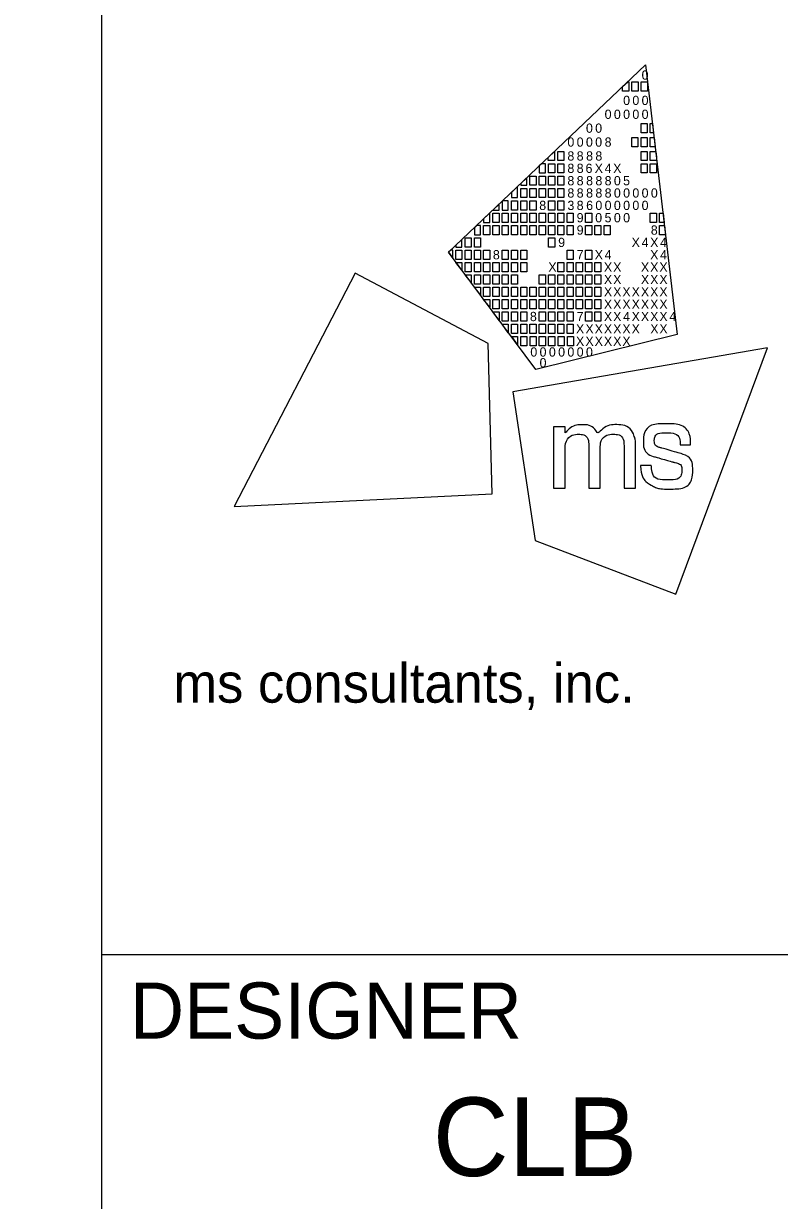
# Model space of a CAD drawing. Extents: x -0.2 to 34, y 0 to 22.
# Drawn here: x 31.86 to 33.207, y 2.061 to 4.16 of the extents above; entities that cross this region are included whole.
import ezdxf

# ---------------------------------------------------------------- set-up
doc = ezdxf.new("R2010")
doc.units = 0
for name, color, linetype in [('SC_Scratch1', 7, 'Continuous'), ('SH_Border', 7, 'Continuous'), ('SH_Data', 7, 'Continuous')]:
    doc.layers.add(name, color=color, linetype=linetype)

msp = doc.modelspace()

# ---------------------------------------------------------------- linework, layer by layer
at = {"layer": 'SC_Scratch1'}
msp.add_lwpolyline([(32, 21.5), (1.5, 21.5), (1.5, 0.5), (32, 0.5)], close=True, dxfattribs=at)
at = {"layer": 'SH_Border'}
for p, q in [((32, 0.5), (32, 21.5)), ((32.6175, 3.7519), (32.9688, 4.0861)), ((32.9688, 4.0861), (32.9688, 4.0861)), ((32.9688, 4.0861), (33.0253, 3.6052)), ((32.773, 3.543), (32.6175, 3.7519)), ((33.0253, 3.6052), (32.773, 3.543)), ((32, 2.5), (33.5, 2.5))]:
    msp.add_line(p, q, dxfattribs=at)
for points in [[(32.9279, 4.0472), (32.9369, 4.0558), (32.9389, 4.0558), (32.9389, 4.0393), (32.9279, 4.0393)], [(32.9444, 4.0558), (32.9554, 4.0558), (32.9554, 4.0393), (32.9444, 4.0393)], [(32.9609, 4.0558), (32.9719, 4.0558), (32.9719, 4.0393), (32.9609, 4.0393)], [(32.9606, 3.9815), (32.9716, 3.9815), (32.9716, 3.965), (32.9606, 3.965)], [(32.9771, 3.9815), (32.9811, 3.9815), (32.983, 3.965), (32.9771, 3.965)], [(32.9441, 3.9567), (32.9551, 3.9567), (32.9551, 3.9402), (32.9441, 3.9402)], [(32.9606, 3.9567), (32.9716, 3.9567), (32.9716, 3.9402), (32.9606, 3.9402)], [(32.9771, 3.9567), (32.984, 3.9567), (32.9859, 3.9402), (32.9771, 3.9402)], [(32.7953, 3.9211), (32.8064, 3.9316), (32.8064, 3.9154), (32.7953, 3.9154)], [(32.8123, 3.9319), (32.8233, 3.9319), (32.8233, 3.9154), (32.8123, 3.9154)], [(32.9606, 3.9319), (32.9716, 3.9319), (32.9716, 3.9154), (32.9606, 3.9154)], [(32.9771, 3.9319), (32.9869, 3.9319), (32.9881, 3.9218), (32.9881, 3.9154), (32.9771, 3.9154)], [(32.7958, 3.9099), (32.8068, 3.9099), (32.8068, 3.8934), (32.7958, 3.8934)], [(32.8123, 3.9099), (32.8233, 3.9099), (32.8233, 3.8934), (32.8123, 3.8934)], [(32.9606, 3.9099), (32.9716, 3.9099), (32.9716, 3.8934), (32.9606, 3.8934)], [(32.9771, 3.9099), (32.9881, 3.9099), (32.9881, 3.8934), (32.9771, 3.8934)], [(32.7627, 3.8879), (32.7737, 3.8879), (32.7737, 3.8714), (32.7627, 3.8714)], [(32.7793, 3.8879), (32.7903, 3.8879), (32.7903, 3.8714), (32.7793, 3.8714)], [(32.7958, 3.8879), (32.8068, 3.8879), (32.8068, 3.8714), (32.7958, 3.8714)], [(32.8123, 3.8879), (32.8233, 3.8879), (32.8233, 3.8714), (32.8123, 3.8714)], [(32.7462, 3.8659), (32.7572, 3.8659), (32.7572, 3.8494), (32.7462, 3.8494)], [(32.7627, 3.8659), (32.7737, 3.8659), (32.7737, 3.8494), (32.7627, 3.8494)], [(32.7793, 3.8659), (32.7903, 3.8659), (32.7903, 3.8494), (32.7793, 3.8494)], [(32.7958, 3.8659), (32.8068, 3.8659), (32.8068, 3.8494), (32.7958, 3.8494)], [(32.8123, 3.8659), (32.8233, 3.8659), (32.8233, 3.8494), (32.8123, 3.8494)], [(32.7297, 3.8439), (32.7407, 3.8439), (32.7407, 3.8273), (32.7297, 3.8273)], [(32.7462, 3.8439), (32.7572, 3.8439), (32.7572, 3.8273), (32.7462, 3.8273)], [(32.7627, 3.8439), (32.7737, 3.8439), (32.7737, 3.8273), (32.7627, 3.8273)], [(32.7958, 3.8439), (32.8068, 3.8439), (32.8068, 3.8273), (32.7958, 3.8273)], [(32.8123, 3.8439), (32.8233, 3.8439), (32.8233, 3.8273), (32.8123, 3.8273)], [(32.6967, 3.8218), (32.7077, 3.8218), (32.7077, 3.8053), (32.6967, 3.8053)], [(32.7132, 3.8218), (32.7242, 3.8218), (32.7242, 3.8053), (32.7132, 3.8053)], [(32.7297, 3.8218), (32.7407, 3.8218), (32.7407, 3.8053), (32.7297, 3.8053)], [(32.7462, 3.8218), (32.7572, 3.8218), (32.7572, 3.8053), (32.7462, 3.8053)], [(32.7627, 3.8218), (32.7737, 3.8218), (32.7737, 3.8053), (32.7627, 3.8053)], [(32.7793, 3.8218), (32.7903, 3.8218), (32.7903, 3.8053), (32.7793, 3.8053)], [(32.7958, 3.8218), (32.8068, 3.8218), (32.8068, 3.8053), (32.7958, 3.8053)], [(32.8123, 3.8218), (32.8233, 3.8218), (32.8233, 3.8053), (32.8123, 3.8053)], [(32.8288, 3.8218), (32.8398, 3.8218), (32.8398, 3.8053), (32.8288, 3.8053)], [(32.8618, 3.8218), (32.8728, 3.8218), (32.8728, 3.8053), (32.8618, 3.8053)], [(32.9771, 3.8218), (32.9881, 3.8218), (32.9881, 3.8053), (32.9771, 3.8053)], [(32.9935, 3.8218), (32.9998, 3.8218), (33.0018, 3.8053), (32.9935, 3.8053)], [(32.6802, 3.7998), (32.6912, 3.7998), (32.6912, 3.7833), (32.6802, 3.7833)], [(32.6967, 3.7998), (32.7077, 3.7998), (32.7077, 3.7833), (32.6967, 3.7833)], [(32.7132, 3.7998), (32.7242, 3.7998), (32.7242, 3.7833), (32.7132, 3.7833)], [(32.7297, 3.7998), (32.7407, 3.7998), (32.7407, 3.7833), (32.7297, 3.7833)], [(32.7462, 3.7998), (32.7572, 3.7998), (32.7572, 3.7833), (32.7462, 3.7833)], [(32.7627, 3.7998), (32.7737, 3.7998), (32.7737, 3.7833), (32.7627, 3.7833)], [(32.7793, 3.7998), (32.7903, 3.7998), (32.7903, 3.7833), (32.7793, 3.7833)], [(32.7958, 3.7998), (32.8068, 3.7998), (32.8068, 3.7833), (32.7958, 3.7833)], [(32.8123, 3.7998), (32.8233, 3.7998), (32.8233, 3.7833), (32.8123, 3.7833)], [(32.8288, 3.7998), (32.8398, 3.7998), (32.8398, 3.7833), (32.8288, 3.7833)], [(32.8618, 3.7998), (32.8728, 3.7998), (32.8728, 3.7833), (32.8618, 3.7833)], [(32.8783, 3.7998), (32.8893, 3.7998), (32.8893, 3.7833), (32.8783, 3.7833)], [(32.8947, 3.7998), (32.9057, 3.7998), (32.9057, 3.7833), (32.8947, 3.7833)], [(32.9935, 3.7998), (33.0024, 3.7998), (33.0044, 3.7833), (32.9935, 3.7833)], [(32.6471, 3.7778), (32.6581, 3.7778), (32.6581, 3.7613), (32.6471, 3.7613)], [(32.6637, 3.7778), (32.6747, 3.7778), (32.6747, 3.7613), (32.6637, 3.7613)], [(32.7958, 3.7778), (32.8068, 3.7778), (32.8068, 3.7613), (32.7958, 3.7613)], [(32.6306, 3.7558), (32.6416, 3.7558), (32.6416, 3.7393), (32.6306, 3.7393)], [(32.6471, 3.7558), (32.6581, 3.7558), (32.6581, 3.7393), (32.6471, 3.7393)], [(32.6637, 3.7558), (32.6747, 3.7558), (32.6747, 3.7393), (32.6637, 3.7393)], [(32.6802, 3.7558), (32.6912, 3.7558), (32.6912, 3.7393), (32.6802, 3.7393)], [(32.7132, 3.7558), (32.7242, 3.7558), (32.7242, 3.7393), (32.7132, 3.7393)], [(32.7297, 3.7558), (32.7407, 3.7558), (32.7407, 3.7393), (32.7297, 3.7393)], [(32.7462, 3.7558), (32.7572, 3.7558), (32.7572, 3.7393), (32.7462, 3.7393)], [(32.8288, 3.7558), (32.8398, 3.7558), (32.8398, 3.7393), (32.8288, 3.7393)], [(32.8618, 3.7558), (32.8728, 3.7558), (32.8728, 3.7393), (32.8618, 3.7393)], [(32.6306, 3.7338), (32.6416, 3.7338), (32.6416, 3.72)], [(32.6471, 3.7338), (32.6581, 3.7338), (32.6581, 3.7173), (32.6471, 3.7173)], [(32.6637, 3.7338), (32.6747, 3.7338), (32.6747, 3.7173), (32.6637, 3.7173)], [(32.6802, 3.7338), (32.6912, 3.7338), (32.6912, 3.7173), (32.6802, 3.7173)], [(32.6967, 3.7338), (32.7077, 3.7338), (32.7077, 3.7173), (32.6967, 3.7173)], [(32.7132, 3.7338), (32.7242, 3.7338), (32.7242, 3.7173), (32.7132, 3.7173)], [(32.7297, 3.7338), (32.7407, 3.7338), (32.7407, 3.7173), (32.7297, 3.7173)], [(32.7462, 3.7338), (32.7572, 3.7338), (32.7572, 3.7173), (32.7462, 3.7173)], [(32.8123, 3.7338), (32.8233, 3.7338), (32.8233, 3.7173), (32.8123, 3.7173)], [(32.8288, 3.7338), (32.8398, 3.7338), (32.8398, 3.7173), (32.8288, 3.7173)], [(32.8453, 3.7338), (32.8563, 3.7338), (32.8563, 3.7173), (32.8453, 3.7173)], [(32.8618, 3.7338), (32.8728, 3.7338), (32.8728, 3.7173), (32.8618, 3.7173)], [(32.8783, 3.7338), (32.8893, 3.7338), (32.8893, 3.7173), (32.8783, 3.7173)], [(32.6471, 3.7117), (32.6581, 3.7117), (32.6581, 3.698)], [(32.6637, 3.7117), (32.6747, 3.7117), (32.6747, 3.6952), (32.6637, 3.6952)], [(32.6802, 3.7117), (32.6912, 3.7117), (32.6912, 3.6952), (32.6802, 3.6952)], [(32.6967, 3.7117), (32.7077, 3.7117), (32.7077, 3.6952), (32.6967, 3.6952)], [(32.7132, 3.7117), (32.7242, 3.7117), (32.7242, 3.6952), (32.7132, 3.6952)], [(32.7297, 3.7117), (32.7407, 3.7117), (32.7407, 3.6952), (32.7297, 3.6952)], [(32.7793, 3.7117), (32.7903, 3.7117), (32.7903, 3.6952), (32.7793, 3.6952)], [(32.7958, 3.7117), (32.8068, 3.7117), (32.8068, 3.6952), (32.7958, 3.6952)], [(32.8123, 3.7117), (32.8233, 3.7117), (32.8233, 3.6952), (32.8123, 3.6952)], [(32.8288, 3.7117), (32.8398, 3.7117), (32.8398, 3.6952), (32.8288, 3.6952)], [(32.8453, 3.7117), (32.8563, 3.7117), (32.8563, 3.6952), (32.8453, 3.6952)], [(32.8618, 3.7117), (32.8728, 3.7117), (32.8728, 3.6952), (32.8618, 3.6952)], [(32.8783, 3.7117), (32.8893, 3.7117), (32.8893, 3.6952), (32.8783, 3.6952)], [(32.6637, 3.6897), (32.6747, 3.6897), (32.6747, 3.676)], [(32.6747, 3.6897), (32.6747, 3.6897), (32.6747, 3.6897)], [(32.6802, 3.6897), (32.6912, 3.6897), (32.6912, 3.6732), (32.6802, 3.6732)], [(32.6967, 3.6897), (32.7077, 3.6897), (32.7077, 3.6732), (32.6967, 3.6732)], [(32.7132, 3.6897), (32.7242, 3.6897), (32.7242, 3.6732), (32.7132, 3.6732)], [(32.7297, 3.6897), (32.7407, 3.6897), (32.7407, 3.6732), (32.7297, 3.6732)], [(32.7462, 3.6897), (32.7572, 3.6897), (32.7572, 3.6732), (32.7462, 3.6732)], [(32.7627, 3.6897), (32.7737, 3.6897), (32.7737, 3.6732), (32.7627, 3.6732)], [(32.7793, 3.6897), (32.7903, 3.6897), (32.7903, 3.6732), (32.7793, 3.6732)], [(32.7958, 3.6897), (32.8068, 3.6897), (32.8068, 3.6732), (32.7958, 3.6732)], [(32.8123, 3.6897), (32.8233, 3.6897), (32.8233, 3.6732), (32.8123, 3.6732)], [(32.8288, 3.6897), (32.8398, 3.6897), (32.8398, 3.6732), (32.8288, 3.6732)], [(32.8453, 3.6897), (32.8563, 3.6897), (32.8563, 3.6732), (32.8453, 3.6732)], [(32.8618, 3.6897), (32.8728, 3.6897), (32.8728, 3.6732), (32.8618, 3.6732)], [(32.8783, 3.6897), (32.8893, 3.6897), (32.8893, 3.6732), (32.8783, 3.6732)], [(32.6802, 3.6677), (32.6912, 3.6677), (32.6912, 3.654)], [(32.6967, 3.6677), (32.7077, 3.6677), (32.7077, 3.6512), (32.6967, 3.6512)], [(32.7132, 3.6677), (32.7242, 3.6677), (32.7242, 3.6512), (32.7132, 3.6512)], [(32.7297, 3.6677), (32.7407, 3.6677), (32.7407, 3.6512), (32.7297, 3.6512)], [(32.7462, 3.6677), (32.7572, 3.6677), (32.7572, 3.6512), (32.7462, 3.6512)], [(32.7627, 3.6677), (32.7737, 3.6677), (32.7737, 3.6512), (32.7627, 3.6512)], [(32.7793, 3.6677), (32.7903, 3.6677), (32.7903, 3.6512), (32.7793, 3.6512)], [(32.7958, 3.6677), (32.8068, 3.6677), (32.8068, 3.6512), (32.7958, 3.6512)], [(32.8123, 3.6677), (32.8233, 3.6677), (32.8233, 3.6512), (32.8123, 3.6512)], [(32.8288, 3.6677), (32.8398, 3.6677), (32.8398, 3.6512), (32.8288, 3.6512)], [(32.8453, 3.6677), (32.8563, 3.6677), (32.8563, 3.6512), (32.8453, 3.6512)], [(32.8618, 3.6677), (32.8728, 3.6677), (32.8728, 3.6512), (32.8618, 3.6512)], [(32.8783, 3.6677), (32.8893, 3.6677), (32.8893, 3.6512), (32.8783, 3.6512)], [(32.7077, 3.6305), (32.6965, 3.6457), (32.7077, 3.6457)], [(32.7132, 3.6457), (32.7242, 3.6457), (32.7242, 3.6292), (32.7132, 3.6292)], [(32.7297, 3.6457), (32.7407, 3.6457), (32.7407, 3.6292), (32.7297, 3.6292)], [(32.7462, 3.6457), (32.7572, 3.6457), (32.7572, 3.6292), (32.7462, 3.6292)], [(32.7793, 3.6457), (32.7903, 3.6457), (32.7903, 3.6292), (32.7793, 3.6292)], [(32.7958, 3.6457), (32.8068, 3.6457), (32.8068, 3.6292), (32.7958, 3.6292)], [(32.8123, 3.6457), (32.8233, 3.6457), (32.8233, 3.6292), (32.8123, 3.6292)], [(32.8288, 3.6457), (32.8398, 3.6457), (32.8398, 3.6292), (32.8288, 3.6292)], [(32.8618, 3.6457), (32.8728, 3.6457), (32.8728, 3.6292), (32.8618, 3.6292)], [(32.8783, 3.6457), (32.8893, 3.6457), (32.8893, 3.6292), (32.8783, 3.6292)], [(32.724, 3.6082), (32.7132, 3.6237), (32.7242, 3.6237)], [(32.7297, 3.6237), (32.7407, 3.6237), (32.7407, 3.6072), (32.7297, 3.6072)], [(32.7462, 3.6237), (32.7572, 3.6237), (32.7572, 3.6072), (32.7462, 3.6072)], [(32.7627, 3.6237), (32.7737, 3.6237), (32.7737, 3.6072), (32.7627, 3.6072)], [(32.7793, 3.6237), (32.7903, 3.6237), (32.7903, 3.6072), (32.7793, 3.6072)], [(32.7958, 3.6237), (32.8068, 3.6237), (32.8068, 3.6072), (32.7958, 3.6072)], [(32.8123, 3.6237), (32.8233, 3.6237), (32.8233, 3.6072), (32.8123, 3.6072)], [(32.8288, 3.6237), (32.8398, 3.6237), (32.8398, 3.6072), (32.8288, 3.6072)], [(32.7302, 3.6017), (32.7407, 3.6017), (32.7408, 3.5875)], [(32.7463, 3.6017), (32.7573, 3.6017), (32.7573, 3.5852), (32.7463, 3.5852)], [(32.763, 3.6017), (32.774, 3.6017), (32.774, 3.5852), (32.763, 3.5852)], [(32.7794, 3.6017), (32.7904, 3.6017), (32.7904, 3.5852), (32.7794, 3.5852)], [(32.796, 3.6017), (32.807, 3.6017), (32.807, 3.5852), (32.796, 3.5852)], [(32.8129, 3.6017), (32.8239, 3.6017), (32.8239, 3.5851), (32.8129, 3.5851)], [(32.8296, 3.6017), (32.8406, 3.6017), (32.8406, 3.5851), (32.8296, 3.5851)]]:
    msp.add_lwpolyline(points, close=True, dxfattribs=at)
for points in [[(32.7903, 3.9099), (32.7836, 3.9099), (32.7793, 3.9058), (32.7793, 3.8934), (32.7903, 3.8934), (32.7903, 3.9099)], [(32.7572, 3.8849), (32.7462, 3.8744), (32.7462, 3.8714), (32.7572, 3.8714), (32.7572, 3.8849)], [(32.7407, 3.8691), (32.7297, 3.8587), (32.7297, 3.8494), (32.7407, 3.8494), (32.7407, 3.8691)], [(32.7242, 3.8439), (32.7141, 3.8439), (32.7132, 3.843), (32.7132, 3.8273), (32.7242, 3.8273), (32.7242, 3.8439)], [(32.6912, 3.822), (32.6802, 3.8115), (32.6802, 3.8053), (32.6912, 3.8053), (32.6912, 3.822)], [(32.7077, 3.8377), (32.6968, 3.8273), (32.7077, 3.8273), (32.7077, 3.8377)], [(32.6747, 3.7998), (32.6679, 3.7998), (32.6637, 3.7958), (32.6637, 3.7833), (32.6747, 3.7833), (32.6747, 3.7998)], [(32.6416, 3.7749), (32.6306, 3.7644), (32.6306, 3.7613), (32.6416, 3.7613), (32.6416, 3.7749)], [(32.6251, 3.7558), (32.6216, 3.7558), (32.6175, 3.7519), (32.6251, 3.7417), (32.6251, 3.7558)], [(32.4512, 3.7149), (32.2359, 3.2988), (32.6956, 3.3215), (32.6884, 3.5892), (32.4512, 3.7149)], [(33.0229, 3.1422), (33.1859, 3.5814), (32.7324, 3.5029), (32.7722, 3.2381), (33.0229, 3.1422)]]:
    msp.add_lwpolyline(points, dxfattribs=at)
for points in [[(32.8048, 3.3315), (32.8048, 3.3315), (32.8048, 3.4409), (32.8048, 3.4409), (32.8048, 3.4409), (32.8255, 3.4409), (32.8255, 3.4409), (32.8255, 3.4409), (32.8255, 3.4297), (32.8255, 3.4297), (32.8346, 3.4399), (32.8457, 3.4445), (32.8555, 3.4445), (32.8688, 3.4445), (32.8791, 3.4372), (32.8837, 3.4266), (32.8915, 3.4381), (32.905, 3.4446), (32.9166, 3.4446), (32.9325, 3.4446), (32.9451, 3.435), (32.9494, 3.4213), (32.9494, 3.4212), (32.9494, 3.4212), (32.9494, 3.4212), (32.9501, 3.419), (32.9506, 3.4172), (32.9506, 3.4071), (32.9506, 3.4071), (32.9506, 3.3314), (32.9506, 3.3314), (32.9506, 3.3314), (32.9303, 3.3314), (32.9303, 3.3314), (32.9303, 3.3314), (32.9303, 3.4048), (32.9303, 3.4048), (32.9303, 3.4201), (32.9219, 3.4274), (32.911, 3.4274), (32.8995, 3.4274), (32.8879, 3.4171), (32.8879, 3.4001), (32.8879, 3.4001), (32.8879, 3.3315), (32.8879, 3.3315), (32.8879, 3.3315), (32.8674, 3.3315), (32.8674, 3.3315), (32.8674, 3.3315), (32.8674, 3.4059), (32.8674, 3.4059), (32.8674, 3.4203), (32.8588, 3.4274), (32.8496, 3.4274), (32.8384, 3.4274), (32.8254, 3.417), (32.8254, 3.3962), (32.8254, 3.3962), (32.8254, 3.3315), (32.8254, 3.3315), (32.8254, 3.3315), (32.8048, 3.3315), (32.8048, 3.3315)], [(32.9595, 3.3709), (32.9595, 3.3709), (32.9595, 3.3717), (32.9595, 3.3717), (32.9595, 3.3717), (32.9603, 3.3717), (32.9603, 3.3717), (32.9603, 3.3717), (32.9783, 3.3717), (32.9783, 3.3717), (32.9783, 3.3717), (32.9789, 3.3717), (32.9789, 3.3717), (32.9789, 3.3717), (32.979, 3.371), (32.979, 3.371), (32.9803, 3.3554), (32.9887, 3.346), (33.009, 3.346), (33.0273, 3.346), (33.0333, 3.3554), (33.0333, 3.3631), (33.0333, 3.3732), (33.0256, 3.3758), (33.0175, 3.378), (33.0175, 3.378), (32.987, 3.3867), (32.987, 3.3867), (32.972, 3.3909), (32.9648, 3.4019), (32.9648, 3.4142), (32.9648, 3.4303), (32.9768, 3.4462), (33.0052, 3.4462), (33.0348, 3.4462), (33.0489, 3.4285), (33.0489, 3.4095), (33.0489, 3.4095), (33.0489, 3.4087), (33.0489, 3.4087), (33.0489, 3.4087), (33.0482, 3.4087), (33.0482, 3.4087), (33.0482, 3.4087), (33.0312, 3.4087), (33.0312, 3.4087), (33.0312, 3.4087), (33.0305, 3.4087), (33.0305, 3.4087), (33.0305, 3.4087), (33.0305, 3.4094), (33.0305, 3.4094), (33.0301, 3.4208), (33.0226, 3.43), (33.0056, 3.43), (32.9891, 3.43), (32.9843, 3.4218), (32.9843, 3.4157), (32.9843, 3.4108), (32.9869, 3.4059), (32.9959, 3.4033), (32.9959, 3.4033), (33.0255, 3.3948), (33.0255, 3.3948), (33.0462, 3.3889), (33.0527, 3.3777), (33.0527, 3.3639), (33.0527, 3.3462), (33.041, 3.3298), (33.0087, 3.3298), (32.9952, 3.3298), (32.9877, 3.3321), (32.9823, 3.3348), (32.969, 3.3414), (32.9609, 3.3536), (32.9595, 3.3709)]]:
    msp.add_open_spline(points, degree=3, dxfattribs=at)
at = {"layer": 'SH_Data'}
msp.add_line((32.75, 3.5), (32.75, 3.5), dxfattribs=at)

# ---------------------------------------------------------------- texts
at = {"layer": 'SH_Border'}
for s, height, p in [('0', 0.0165, (32.9617, 4.0597)), ('0', 0.0165, (32.9288, 4.0145)), ('0', 0.0165, (32.9452, 4.0145)), ('0', 0.0165, (32.9617, 4.0145)), ('0', 0.0165, (32.8958, 3.9897)), ('0', 0.0165, (32.9123, 3.9897)), ('0', 0.0165, (32.9288, 3.9897)), ('0', 0.0165, (32.9452, 3.9897)), ('0', 0.0165, (32.9617, 3.9897)), ('0', 0.0165, (32.8625, 3.965)), ('0', 0.0165, (32.879, 3.965)), ('0', 0.0165, (32.8295, 3.9402)), ('0', 0.0165, (32.846, 3.9402)), ('0', 0.0165, (32.8625, 3.9402)), ('0', 0.0165, (32.879, 3.9402)), ('8', 0.0165, (32.8958, 3.9402)), ('8', 0.0165, (32.8295, 3.9154)), ('8', 0.0165, (32.846, 3.9154)), ('8', 0.0165, (32.8628, 3.9154)), ('8', 0.0165, (32.8793, 3.9154)), ('8', 0.0165, (32.8295, 3.8934)), ('8', 0.0165, (32.846, 3.8934)), ('6', 0.0165, (32.8618, 3.8934)), ('X', 0.0165, (32.8781, 3.8934)), ('4', 0.0165, (32.8958, 3.8934)), ('X', 0.0165, (32.911, 3.8934)), ('8', 0.0165, (32.8295, 3.8713)), ('8', 0.0165, (32.846, 3.8713)), ('8', 0.0165, (32.8628, 3.8713)), ('8', 0.0165, (32.8794, 3.8713)), ('8', 0.0165, (32.8958, 3.8713)), ('0', 0.0165, (32.9123, 3.8713)), ('5', 0.0165, (32.9287, 3.8713)), ('8', 0.0165, (32.8295, 3.8494)), ('8', 0.0165, (32.846, 3.8494)), ('8', 0.0165, (32.8628, 3.8494)), ('8', 0.0165, (32.8794, 3.8494)), ('8', 0.0165, (32.8958, 3.8494)), ('0', 0.0165, (32.9123, 3.8494)), ('0', 0.0165, (32.9288, 3.8494)), ('0', 0.0165, (32.9452, 3.8494)), ('0', 0.0165, (32.9617, 3.8494)), ('0', 0.0165, (32.9782, 3.8494)), ('8', 0.0165, (32.7793, 3.8273)), ('3', 0.0165, (32.8295, 3.8273)), ('8', 0.0165, (32.846, 3.8273)), ('6', 0.0165, (32.8629, 3.8273)), ('0', 0.0165, (32.8793, 3.8273)), ('0', 0.0165, (32.8958, 3.8273)), ('0', 0.0165, (32.9123, 3.8273)), ('0', 0.0165, (32.9288, 3.8273)), ('0', 0.0165, (32.9452, 3.8273)), ('0', 0.0165, (32.9617, 3.8273)), ('9', 0.0165, (32.846, 3.8053)), ('0', 0.0165, (32.879, 3.8053)), ('5', 0.0165, (32.8957, 3.8053)), ('0', 0.0165, (32.9123, 3.8053)), ('0', 0.0165, (32.9288, 3.8053)), ('9', 0.0165, (32.846, 3.7833)), ('8', 0.0165, (32.9781, 3.7833)), ('9', 0.0165, (32.813, 3.7613)), ('X', 0.0165, (32.9439, 3.7613)), ('4', 0.0165, (32.9617, 3.7613)), ('X', 0.0165, (32.9769, 3.7613)), ('4', 0.0165, (32.9946, 3.7613)), ('8', 0.0165, (32.6967, 3.7393)), ('7', 0.0165, (32.846, 3.7393)), ('X', 0.0165, (32.8781, 3.7393)), ('4', 0.0165, (32.8958, 3.7393)), ('X', 0.0165, (32.9769, 3.7393)), ('4', 0.0165, (32.9946, 3.7393)), ('X', 0.0165, (32.7955, 3.7173)), ('X', 0.0165, (32.8945, 3.7173)), ('X', 0.0165, (32.911, 3.7173)), ('X', 0.0165, (32.9604, 3.7173)), ('X', 0.0165, (32.9769, 3.7173)), ('X', 0.0165, (32.9933, 3.7173)), ('X', 0.0165, (32.8945, 3.6952)), ('X', 0.0165, (32.911, 3.6952)), ('X', 0.0165, (32.9604, 3.6952)), ('X', 0.0165, (32.9769, 3.6952)), ('X', 0.0165, (32.9933, 3.6952)), ('X', 0.0165, (32.8945, 3.6732)), ('X', 0.0165, (32.911, 3.6732)), ('X', 0.0165, (32.9274, 3.6732)), ('X', 0.0165, (32.9439, 3.6732)), ('X', 0.0165, (32.9604, 3.6732)), ('X', 0.0165, (32.9769, 3.6732)), ('X', 0.0165, (32.9933, 3.6732)), ('X', 0.0165, (32.8945, 3.6512)), ('X', 0.0165, (32.911, 3.6512)), ('X', 0.0165, (32.9274, 3.6512)), ('X', 0.0165, (32.9439, 3.6512)), ('X', 0.0165, (32.9604, 3.6512)), ('X', 0.0165, (32.9769, 3.6512)), ('X', 0.0165, (32.9933, 3.6512)), ('8', 0.0165, (32.7627, 3.6292)), ('7', 0.0165, (32.846, 3.6292)), ('X', 0.0165, (32.8945, 3.6292)), ('X', 0.0165, (32.911, 3.6292)), ('4', 0.0165, (32.9288, 3.6292)), ('X', 0.0165, (32.9439, 3.6292)), ('X', 0.0165, (32.9604, 3.6292)), ('X', 0.0165, (32.9769, 3.6292)), ('X', 0.0165, (32.9933, 3.6292)), ('4', 0.0165, (33.0111, 3.6292)), ('X', 0.0165, (32.8447, 3.6072)), ('X', 0.0165, (32.8616, 3.6072)), ('X', 0.0165, (32.878, 3.6072)), ('X', 0.0165, (32.8945, 3.6072)), ('X', 0.0165, (32.911, 3.6072)), ('X', 0.0165, (32.9274, 3.6072)), ('X', 0.0165, (32.9439, 3.6072)), ('X', 0.0165, (32.9771, 3.6072)), ('X', 0.0165, (32.9933, 3.6072)), ('X', 0.0165, (32.8447, 3.5851)), ('X', 0.0165, (32.8616, 3.5851)), ('X', 0.0165, (32.878, 3.5851)), ('X', 0.0165, (32.8945, 3.5851)), ('X', 0.0165, (32.911, 3.5851)), ('X', 0.0165, (32.9274, 3.5851)), ('0', 0.0165, (32.7634, 3.5659)), ('0', 0.0165, (32.7799, 3.5659)), ('0', 0.0165, (32.7965, 3.5659)), ('0', 0.0165, (32.813, 3.5659)), ('0', 0.0165, (32.8295, 3.5659)), ('0', 0.0165, (32.846, 3.5659)), ('0', 0.0165, (32.8625, 3.5659)), ('0', 0.0165, (32.7799, 3.5467)), ('ms consultants, inc.', 0.07, (32.1273, 2.9489))]:
    msp.add_text(s, height=height, rotation=360, dxfattribs=at).set_placement(p)
at = {"layer": 'SH_Data'}
for s, height, p in [('DESIGNER', 0.1, (32.05, 2.35)), ('CLB', 0.14, (32.5896, 2.105))]:
    msp.add_text(s, height=height, dxfattribs=at).set_placement(p)

doc.saveas('drawing.dxf')
